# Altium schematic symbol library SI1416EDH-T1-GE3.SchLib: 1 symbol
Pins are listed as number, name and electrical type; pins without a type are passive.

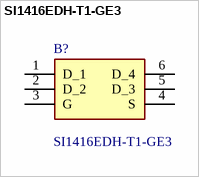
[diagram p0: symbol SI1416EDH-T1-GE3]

## SI1416EDH-T1-GE3
designator B?
Si1416EDH-T1-GE3 N-Channel MOSFET, 3.9 A, 30 V, 6-Pin SOT-363 Vishay; Geometry.Height: 1.1mm
footprint SOT65P210X110-6N
pins: 1 D_1, 2 D_2, 3 G, 4 S, 5 D_3, 6 D_4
